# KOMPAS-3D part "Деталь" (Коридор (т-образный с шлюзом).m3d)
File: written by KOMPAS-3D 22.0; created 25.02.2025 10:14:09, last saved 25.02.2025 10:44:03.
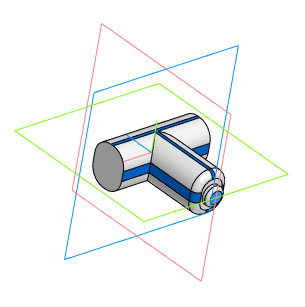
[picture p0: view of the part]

Document properties: Автор: Пользователь Windows; Полное имя файла: C:\Users\Student\Documents\Картошечка\База Сабнатика\Коридор\Коридор (т-образный с шлюзом).m3d

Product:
- Body: Тело 1
    Масса: 0.04792
- Part/product: Деталь
    Масса: 0.046079

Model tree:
1. Эскиз:1
2. Элемент выдавливания:1
     Расстояние 1 = 30
3. Эскиз:2
4. Элемент выдавливания:2
     Расстояние 1 = 20
5. Элемент выдавливания:3  (with: Элемент выдавливания:2)
     Расстояние 1 = 3
6. Скругление:1  (with: Элемент выдавливания:3)
     Радиус = 2
7. Эскиз:3  (with: Элемент выдавливания:3)
8. Элемент выдавливания:4
     Расстояние 1 = 2
9. Скругление:2  (with: Элемент выдавливания:4)
     Радиус = 1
